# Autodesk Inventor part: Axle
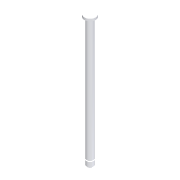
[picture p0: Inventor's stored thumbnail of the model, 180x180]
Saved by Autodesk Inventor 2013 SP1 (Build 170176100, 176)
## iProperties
Created: 2013-01
Part Number: Axle
Material: Aluminum 6061
Document SubType Name: Modeling
Designer: banachd
Density: 1 g/cm^3
Description: 3 mm DIA x 55.5 mm
Author: banachd
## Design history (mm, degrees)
sketch "Sketch1"
  geometry: C1 r 1.5 at (0, 0); 1 further point
  constraints: 1 centre point, 1 coincident
  dimensions: "d0" = 3 diameter of C1
extrude "Extrusion1" new body sketch "Sketch1" distance "d1" = 55.5; taper "d2" = 0 deg
sketch "Sketch2"
  geometry: C1 r 1.5 at (0, 0) reference; C2 r 2.5 at (0, 0)
  constraints: 1 centre point, 1 coincident
  dimensions: "d3" = 5 diameter of C2
extrude "Extrusion2" join sketch "Sketch2" distance "d4" = 1; taper "d5" = 0 deg
sketch "Sketch3"
  geometry: L1 (-1.5, 55.5)-(-2.5, 55.5) reference; L2 (-2.5, 55.5)-(-2.5, 56.5) reference; L3 (-2.5, 56.5)-(2.5, 56.5) reference; L4 (2.5, 56.5)-(2.5, 55.5) reference; L5 (2.5, 55.5)-(1.5, 55.5) reference; L6 (1.5, 55.5)-(1.5, 0) reference; L7 (1.5, 0)-(-1.5, 0) reference; L8 (-1.5, 0)-(-1.5, 55.5) reference; L9 (1.5, 1.5)-(1, 1.5); L10 (1, 1.5)-(1, 1); L11 (1, 1)-(1.5, 1); L12 (1.5, 1)-(1.5, 1.5); L13 (0, -11.4)-(0, 68.4) reference; 1 further point
  constraints: 8 end point, 2 parallel, 1 horizontal, 1 perpendicular, 1 point on line
  dimensions: "d6" = 54 distance from line of L5.end L9; "d7" = 0.5 distance between parallel lines of L11 L9; "d8" = 0.5 distance of L10.end L11.end
revolve "Revolution1" sketch "Sketch3" stored, may be unused: angle "d9" = 90 deg
chamfer "Chamfer1" distance "d11" = 0.5; stored, may be unused: second distance "d12" = 2, angle "d13" = 45 deg
body "Solid1"
node "Project Cut Edges1"
